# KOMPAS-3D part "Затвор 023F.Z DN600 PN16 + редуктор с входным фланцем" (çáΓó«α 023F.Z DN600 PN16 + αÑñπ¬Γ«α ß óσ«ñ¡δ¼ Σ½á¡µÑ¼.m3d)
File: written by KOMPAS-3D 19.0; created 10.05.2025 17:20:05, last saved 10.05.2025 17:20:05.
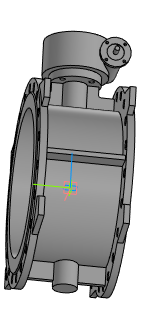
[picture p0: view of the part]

Document properties: Полное имя файла: Затвор 023F.Z DN600 PN16 + редуктор с входным фланцем.a3d

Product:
- Part/product: Затвор 023F.Z DN600 PN16 + редуктор с входным фланцем
    Масса: 476.526

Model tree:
1. Операция без истории:1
